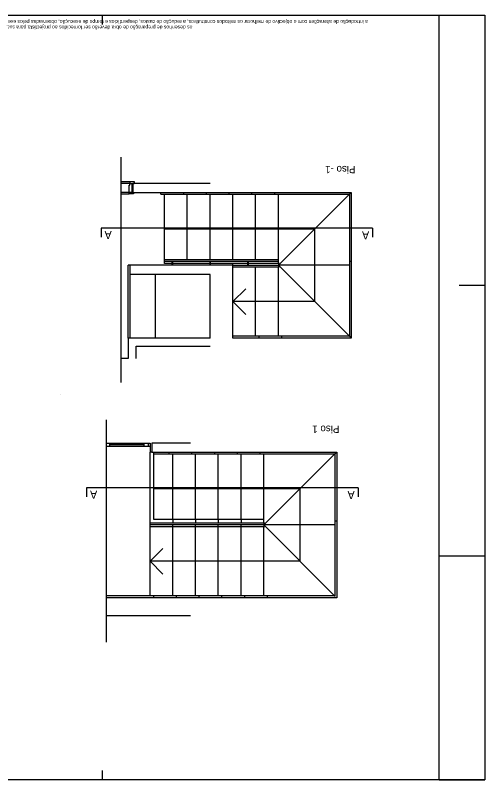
# Model space of a CAD drawing. Extents: x 1290.6 to 1307.2, y -290.6 to -281.7.
# Drawn here: x 1302.04 to 1307.19, y -290.6 to -282.2 of the extents above; entities that cross this region are included whole.
import ezdxf

# ---------------------------------------------------------------- set-up
doc = ezdxf.new("R2010")
doc.units = 0
for name, color, linetype in [('Level 1', 7, 'Continuous'), ('Level 10', 7, 'Continuous'), ('Level 13', 7, 'Continuous'), ('Level 2', 7, 'Continuous'), ('Level 36', 7, 'Continuous'), ('Level 4', 7, 'Continuous'), ('Level 59', 7, 'Continuous'), ('Level 60', 7, 'Continuous'), ('Level 62', 7, 'Continuous')]:
    doc.layers.add(name, color=color, linetype=linetype)

msp = doc.modelspace()

# ---------------------------------------------------------------- linework, layer by layer
at = {"layer": 'Level 1'}
for p, q in [((1303.3267, -284.04725), (1303.3267, -284.05725)), ((1303.3267, -284.04725), (1303.3267, -284.14725)), ((1303.3267, -284.13725), (1303.3267, -284.14725)), ((1303.3267, -284.14725), (1305.7267, -284.14725)), ((1305.7267, -284.14725), (1305.7267, -285.74725)), ((1304.4267, -284.94725), (1303.2967, -284.94725)), ((1303.2967, -284.94725), (1303.2967, -285.04725)), ((1304.4267, -285.74725), (1304.4267, -284.94725)), ((1304.1767, -285.04725), (1303.2967, -285.04725)), ((1304.1767, -285.74725), (1304.1767, -285.04725)), ((1304.1767, -285.74725), (1303.2767, -285.74725)), ((1303.2767, -285.74725), (1303.2767, -285.97225)), ((1305.7267, -285.74725), (1304.4267, -285.74725)), ((1303.3667, -285.83725), (1304.1767, -285.83725)), ((1303.3667, -285.97225), (1303.3667, -285.83725)), ((1303.2767, -285.97225), (1303.19946, -285.97225)), ((1303.96246, -286.90064), (1303.53746, -286.90064)), ((1303.53746, -286.90064), (1303.53746, -287.00064)), ((1303.53746, -287.00064), (1305.56746, -287.00064)), ((1305.56746, -287.00064), (1305.56746, -288.60064)), ((1305.56746, -288.60064), (1303.04022, -288.60064)), ((1303.96246, -288.80064), (1303.04022, -288.80064))]:
    msp.add_line(p, q, dxfattribs=at)
msp.add_lwpolyline([(1304.1767, -284.04725), (1303.3267, -284.04725)], dxfattribs=at)
at = {"layer": 'Level 10'}
for p, q in [((1303.2967, -284.04725), (1303.19946, -284.04725)), ((1303.2867, -284.14725), (1303.19946, -284.14725))]:
    msp.add_line(p, q, dxfattribs=at)
at = {"layer": 'Level 13'}
for p, q in [((1303.2867, -284.14725), (1303.2867, -284.06725)), ((1303.2867, -284.06725), (1303.2967, -284.06725)), ((1303.3467, -284.03225), (1303.2967, -284.03225)), ((1303.2967, -284.03225), (1303.2967, -284.04725)), ((1303.2967, -284.06725), (1303.2967, -284.04725)), ((1303.2967, -284.04725), (1303.3167, -284.04725)), ((1303.2967, -284.04725), (1303.3417, -284.04725)), ((1303.3167, -284.04725), (1303.3167, -284.14725)), ((1303.3417, -284.04725), (1303.3417, -284.04225)), ((1303.3417, -284.04225), (1303.3467, -284.04225)), ((1303.3467, -284.04225), (1303.3467, -284.03225)), ((1303.3167, -284.14725), (1303.2867, -284.14725)), ((1303.2867, -284.16225), (1303.2867, -284.14725)), ((1303.2867, -284.14725), (1303.3317, -284.14725)), ((1303.3367, -284.16225), (1303.2867, -284.16225)), ((1303.3317, -284.14725), (1303.3317, -284.15225)), ((1303.3317, -284.15225), (1303.3367, -284.15225)), ((1303.3367, -284.15225), (1303.3367, -284.16225)), ((1303.6367, -284.16725), (1303.6367, -284.14725)), ((1303.6367, -284.16725), (1305.7067, -284.16725)), ((1303.8867, -284.16725), (1303.8867, -284.14725)), ((1304.1367, -284.16725), (1304.1367, -284.14725)), ((1304.3867, -284.16725), (1304.3867, -284.14725)), ((1304.6367, -284.16725), (1304.6367, -284.14725)), ((1304.8867, -284.16725), (1304.8867, -284.14725)), ((1305.7067, -284.16725), (1305.7267, -284.14725)), ((1305.7067, -284.16725), (1305.7067, -285.72725)), ((1305.7267, -284.90725), (1305.7067, -284.90725)), ((1303.2767, -285.74725), (1303.2767, -284.94725)), ((1303.2967, -284.94725), (1303.2767, -284.94725)), ((1303.2967, -284.94725), (1303.2967, -285.74725)), ((1305.7067, -285.72725), (1304.4267, -285.72725)), ((1304.7167, -285.74725), (1304.7167, -285.72725)), ((1304.9667, -285.74725), (1304.9667, -285.72725)), ((1305.7067, -285.72725), (1305.7267, -285.74725)), ((1303.04022, -286.90064), (1303.51746, -286.90064)), ((1303.04022, -286.93564), (1303.51746, -286.93564)), ((1303.07013, -286.90064), (1303.07013, -286.93564)), ((1303.45046, -286.90064), (1303.45046, -286.93564)), ((1303.49546, -286.90064), (1303.49546, -286.93564)), ((1303.49746, -286.90064), (1303.49746, -286.93564)), ((1303.51746, -286.90064), (1303.51746, -287.00064)), ((1303.53746, -287.00064), (1303.51746, -287.00064)), ((1303.55746, -287.02064), (1305.54746, -287.02064)), ((1303.72746, -287.02064), (1303.72746, -287.00064)), ((1303.97746, -287.02064), (1303.97746, -287.00064)), ((1304.22746, -287.02064), (1304.22746, -287.00064)), ((1304.47746, -287.02064), (1304.47746, -287.00064)), ((1304.72746, -287.02064), (1304.72746, -287.00064)), ((1305.54746, -287.02064), (1305.56746, -287.00064)), ((1305.54746, -287.02064), (1305.54746, -288.58064)), ((1305.56746, -287.76064), (1305.54746, -287.76064)), ((1305.54746, -288.58064), (1303.04022, -288.58064)), ((1303.55746, -288.60064), (1303.55746, -288.58064)), ((1303.80746, -288.60064), (1303.80746, -288.58064)), ((1304.05746, -288.60064), (1304.05746, -288.58064)), ((1304.30746, -288.60064), (1304.30746, -288.58064)), ((1304.55746, -288.60064), (1304.55746, -288.58064)), ((1304.80746, -288.60064), (1304.80746, -288.58064))]:
    msp.add_line(p, q, dxfattribs=at)
at = {"layer": 'Level 2'}
for p, q in [((1303.6767, -284.92725), (1303.6767, -284.16725)), ((1303.9267, -284.88725), (1303.9267, -284.16725)), ((1304.1767, -284.88725), (1304.1767, -284.16725)), ((1304.4267, -284.88725), (1304.4267, -284.16725)), ((1304.6767, -284.88725), (1304.6767, -284.16725)), ((1304.9267, -284.91725), (1304.9267, -284.16725)), ((1304.9267, -284.94725), (1305.7067, -284.16725)), ((1303.6767, -284.54725), (1305.3267, -284.54725)), ((1305.3267, -285.34725), (1305.3267, -284.54725)), ((1304.9267, -284.88725), (1303.6767, -284.88725)), ((1304.9267, -284.92725), (1303.6767, -284.92725)), ((1303.76114, -284.94725), (1303.76114, -284.92725)), ((1303.76782, -284.94725), (1303.76782, -284.92725)), ((1304.17621, -284.94725), (1304.17621, -284.92725)), ((1304.18289, -284.94725), (1304.18289, -284.92725)), ((1304.4267, -284.94725), (1304.4267, -284.92725)), ((1304.9267, -284.91725), (1304.9267, -284.97725)), ((1304.9267, -284.96725), (1304.4267, -284.96725)), ((1304.6767, -285.72725), (1304.6767, -284.96725)), ((1305.7067, -284.94725), (1304.9267, -284.94725)), ((1304.9267, -284.94725), (1305.7067, -285.72725)), ((1304.9267, -285.72725), (1304.9267, -284.97725)), ((1303.5767, -285.74725), (1303.5767, -285.04725)), ((1304.56812, -285.20583), (1304.4267, -285.34725)), ((1304.56812, -285.48867), (1304.4267, -285.34725)), ((1305.3267, -285.34725), (1304.4267, -285.34725)), ((1302.53473, -286.36357), (1302.53291, -286.36539)), ((1302.53473, -286.36357), (1302.53291, -286.36539)), ((1303.51746, -287.00064), (1303.51746, -287.00064)), ((1303.51746, -287.83064), (1303.51746, -287.00064)), ((1303.55746, -287.74064), (1303.55746, -287.00064)), ((1303.76746, -287.74064), (1303.76746, -287.02064)), ((1304.01746, -287.74064), (1304.01746, -287.02064)), ((1304.26746, -287.74064), (1304.26746, -287.02064)), ((1304.51746, -287.74064), (1304.51746, -287.02064)), ((1304.76746, -287.77064), (1304.76746, -287.02064)), ((1304.76746, -287.80064), (1305.54746, -287.02064)), ((1303.55746, -287.40064), (1305.16746, -287.40064)), ((1305.16746, -288.20064), (1305.16746, -287.40064)), ((1304.76746, -287.78064), (1303.51746, -287.78064)), ((1304.76746, -287.74064), (1303.55746, -287.74064)), ((1304.76746, -287.77064), (1304.76746, -287.83064)), ((1304.76746, -287.82064), (1303.51746, -287.82064)), ((1303.51746, -288.58064), (1303.51746, -287.83064)), ((1303.76746, -288.58064), (1303.76746, -287.82064)), ((1304.01746, -288.58064), (1304.01746, -287.82064)), ((1304.26746, -288.58064), (1304.26746, -287.82064)), ((1304.51746, -288.58064), (1304.51746, -287.82064)), ((1305.54746, -287.80064), (1304.76746, -287.80064)), ((1304.76746, -287.80064), (1305.55246, -288.58564)), ((1304.76746, -288.58064), (1304.76746, -287.83064)), ((1303.65888, -288.05922), (1303.51746, -288.20064)), ((1305.16746, -288.20064), (1303.51746, -288.20064)), ((1303.65888, -288.34206), (1303.51746, -288.20064))]:
    msp.add_line(p, q, dxfattribs=at)
at = {"layer": 'Level 36'}
for p, q in [((1303.45046, -286.91714), (1303.07013, -286.91714)), ((1303.45046, -286.91914), (1303.07013, -286.91914))]:
    msp.add_line(p, q, dxfattribs=at)
at = {"layer": 'Level 4'}
for p, q in [((1303.2967, -284.03225), (1303.19946, -284.03225)), ((1303.19946, -284.16225), (1303.2867, -284.16225)), ((1304.9267, -284.90725), (1303.6767, -284.90725)), ((1303.76114, -284.92858), (1303.76114, -284.90725)), ((1303.76782, -284.92858), (1303.76782, -284.90725)), ((1304.17621, -284.92858), (1304.17621, -284.90725)), ((1304.18289, -284.92725), (1304.18289, -284.90725)), ((1304.59084, -284.94725), (1304.59084, -284.90725)), ((1304.59752, -284.94725), (1304.59752, -284.90725)), ((1304.4267, -284.94725), (1304.9267, -284.94725)), ((1303.76746, -287.74064), (1303.76746, -287.78064)), ((1304.01746, -287.74064), (1304.01746, -287.78064)), ((1304.26746, -287.74064), (1304.26746, -287.78064)), ((1304.51746, -287.74064), (1304.51746, -287.78064)), ((1304.76746, -287.79864), (1303.51746, -287.79864)), ((1303.76746, -287.82064), (1303.76746, -287.79864)), ((1304.01746, -287.82064), (1304.01746, -287.79864)), ((1304.26746, -287.82064), (1304.26746, -287.79864)), ((1304.51746, -287.82064), (1304.51746, -287.79864))]:
    msp.add_line(p, q, dxfattribs=at)
at = {"layer": 'Level 59'}
for p, q in [((1303.19946, -286.23721), (1303.19946, -283.7599)), ((1305.96259, -284.53948), (1302.97954, -284.53948)), ((1302.97954, -284.53948), (1302.97954, -284.63928)), ((1305.96259, -284.53948), (1305.96259, -284.63928)), ((1303.04022, -289.08929), (1303.04022, -286.64731)), ((1305.80335, -287.39287), (1302.8203, -287.39287)), ((1302.8203, -287.39287), (1302.8203, -287.49267)), ((1305.80335, -287.39287), (1305.80335, -287.49267))]:
    msp.add_line(p, q, dxfattribs=at)
at = {"layer": 'Level 62'}
for p, q in [((1302.99396, -282.3006), (1302.99396, -282.2006)), ((1306.69356, -290.6006), (1306.69356, -282.2006)), ((1307.19356, -285.1706), (1306.91356, -285.1706)), ((1306.69356, -288.1406), (1307.19356, -288.1406)), ((1302.99316, -290.5006), (1302.99316, -290.6006)), ((1306.69356, -290.6006), (1307.19356, -290.6006))]:
    msp.add_line(p, q, dxfattribs=at)
msp.add_lwpolyline([(1307.19356, -282.2006), (1307.19356, -290.6006), (1295.59396, -290.6006), (1295.59396, -282.2006)], close=True, dxfattribs=at)

# ---------------------------------------------------------------- texts
at = {"layer": 'Level 59'}
for rotation, p in [(180.000181, (1303.09611, -284.5713)), (179.999819, (1305.92457, -284.57514)), (180.000181, (1302.93687, -287.42469)), (179.999819, (1305.76533, -287.42853))]:
    msp.add_text('A', height=0.088, rotation=rotation, dxfattribs=at).set_placement(p)
at = {"layer": 'Level 60'}
for s, height, rotation, p in [('os desenhos de preparação de obra deverão ser fornecidos ao projectista para sua aprovação -', 0.0399996, 180, (1303.98275, -282.3136)), ('a introdução de alterações com o objectivo de melhorar os métodos construtivos, a redução de custos, desperdícios e tempo de execução, observadas pelos exe', 0.0399996, 180, (1305.91175, -282.2526)), ('Piso -1', 0.08, 180.000011, (1305.77396, -283.85579)), ('Piso 1', 0.08, 180.000011, (1305.59695, -286.70918))]:
    msp.add_text(s, height=height, rotation=rotation, dxfattribs=at).set_placement(p)

doc.saveas('drawing.dxf')
